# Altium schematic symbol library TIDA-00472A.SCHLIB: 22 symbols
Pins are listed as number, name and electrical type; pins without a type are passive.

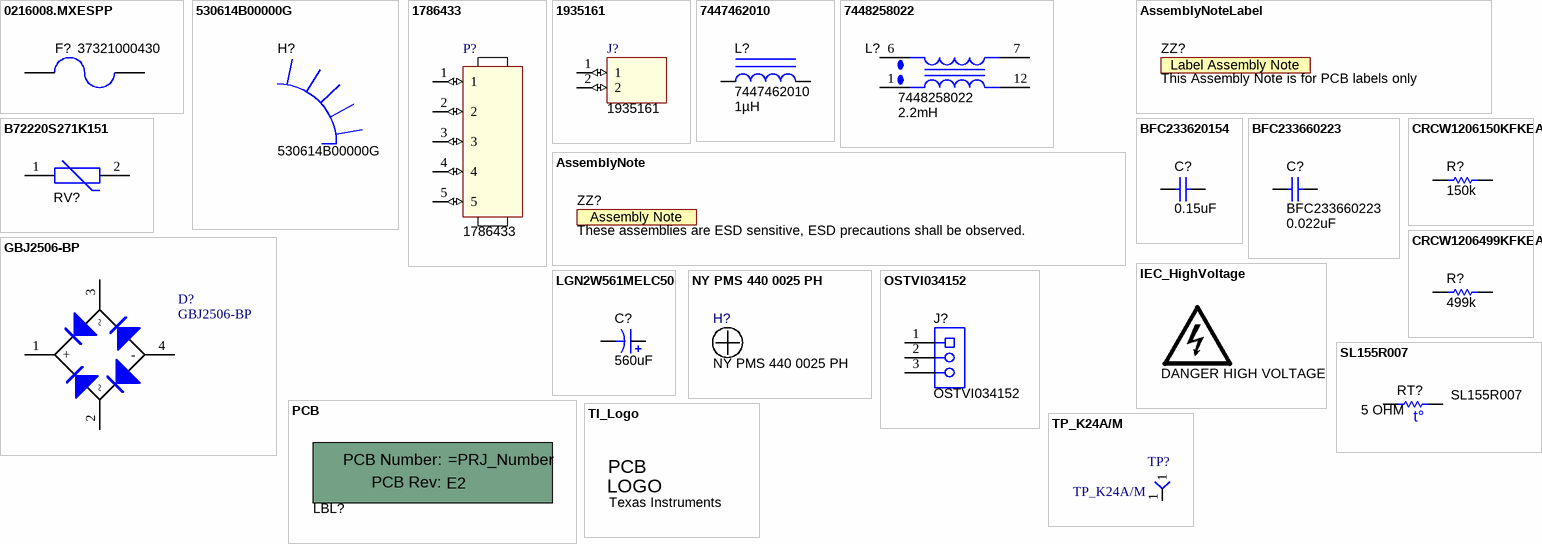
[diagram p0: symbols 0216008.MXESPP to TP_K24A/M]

## 0216008.MXESPP
designator F?, comment 37321000430
LITTELFUSE_373, TH-2P; Manufacturer: Littelfuse Inc; CompType: Fuse; U/M: EA; OpeningTime_200%_max: 30; VDC_V: 250; Irating_A: 8; Rtyp_Ohm: 0.0123; Soldering_Wave_MaxTemp_C: 260; Soldering_Wave_MaxTime_s: 5
footprint FUSE_37321000430 (LITTELFUSE_373, TH-2P)
pins: 1, 2

## 530614B00000G
designator H?
Heat Sink, TO-220, TH; Manufacturer: Aavid; SymbolCreator: a0412235
footprint Aavid_530614B00000G (Aavid)

## 1786433
designator P?
TERM BLOCK HDR 5POS R/A 5.08MM; Manufacturer: PHOENIX CONTACT; SymbolCreator: x0199378; CompType: Terminal Block
footprint PHOENIX_1786433 (TERM BLOCK, HDR, 5POS, R/A 5.08MM)
pins: 1 (io), 2 (io), 3 (io), 4 (io), 5 (io)

## 1935161
designator J?
TERM BLOCK PCB, 2POS, 5.0MM, TH; Manufacturer: PHOENIX CONTACT; SymbolCreator: x0199378; CompType: Terminal Block
footprint Phoenix_1935161 (TERM BLOCK PCB, 2POS, 5.0MM, TH)
pins: 1 (io), 2 (io)

## 7447462010
designator L?  ValueDisplayed: 1µH
Inductor, Unshielded Drum Core, Ferrite, 1uH, 8A, 0.006 ohm, TH; Manufacturer: Wurth Elektronik eiSos; Ind_H: 1.0E-6; Imax_A: 8; Irms: 8.5A @ 40C rise; Isat: 8A @ 10% inductance drop; DCR_ohm: 0.006; U/M: EA
signal-integrity model Inductor
simulation model Inductor
footprint IND_WE-TI_XS
pins: 1, 2

## 7448258022
designator L?  value 2.2mH
FILTER, WE-CMB COMMON MODE POWER LINE CHOKE, 2.2mH, 8A, VERTICAL; Manufacturer: Wurth Elektronics; SymbolCreator: x0199378
footprint WURTH_7448258022 (CHOKE TOROID, 2.2MH, 8A, VERTICAL)
pins: 1, 6, 7, 12 2

## AssemblyNote
designator ZZ?, comment These assemblies are ESD sensitive, ESD precautions shall be observed.  (no BOM)
SymbolCreator: codlsc; CompType: AssemblyNote
footprint AssemblyNote

## AssemblyNoteLabel
designator ZZ?, comment This Assembly Note is for PCB labels only  (no BOM)
SymbolCreator: a0412235
footprint AssemblyNoteLabel

## B72220S271K151
designator RV?  (value not drawn)
VARISTOR, 387V, 8KA, DISC 20MM; Manufacturer: EPCOS Inc; SymbolCreator: x0199378
footprint VAR_B72220S0271K151 (VARISTOR, 275V, 8KA, DISC 20MM)
pins: 1, 2

## BFC233620154
designator C?  value 0.15uF  (hidden comment: BFC233620154)
CAP, FILM, 0.15uF, 310V, 20%, RADIAL-2P; Manufacturer: VISHYA; CompType: Film Capacitor; SymbolCreator: x0199378
footprint B32922_12mm (Epcos film capacitors, 15mm spacing)
pins: 1, 2

## BFC233660223
designator C?  value 0.022uF
CAP, FILM, 0.022uF, 300V, 20%, RADIAL-2P; Manufacturer: VISHYA; CompType: Film Capacitor; SymbolCreator: x0199378
footprint B81123_1800x900x1750 (CAPACITOR, FILM, 4700PF, RADIAL, EPCOS)
pins: 1, 2

## CRCW1206150KFKEA
designator R?  value 150k  (hidden comment: CRCW1206150KFKEA)
RES, 150k ohm, 1%, 0.25W, 1206; Manufacturer: Vishay-Dale; CompType: Resistor; Res_ohm: 150000; Tolerance_%: 1; Power_W: 0.25; VDC_V: 200; TempCo: 100 ppm/C; EIA_Code: E96; U/M: EA
signal-integrity model Resistor
simulation model Resistor
footprint 1206 (1206 from SM-752 data)
footprint 1206M
footprint 1206L
pins: 1, 2

## CRCW1206499KFKEA
designator R?  value 499k  (hidden comment: CRCW1206499KFKEA)
RES, 499k ohm, 1%, 0.25W, 1206; Manufacturer: Vishay-Dale; CompType: Resistor; Res_ohm: 499000; Tolerance_%: 1; Power_W: 0.25; VDC_V: 200; TempCo: 100 ppm/C; EIA_Code: E96; U/M: EA
signal-integrity model Resistor
simulation model Resistor
footprint 1206
footprint 1206M
footprint 1206L
pins: 1, 2

## GBJ2506-BP
designator D?
BRIDGE RECTIFIER, GPP, 25A, 600V, GBJ; Manufacturer: MICRO COMMERCIAL COMPONENTS; SymbolCreator: x0199378
footprint MCC_GBJ2506 (Bridge Rectifier, 4pin , TH)
pins: 1 +, 2 ~, 3 ~, 4 -

## IEC_HighVoltage
designator LOGO?, comment DANGER HIGH VOLTAGE  (no BOM)
IEC 61010-1 High Voltage Warning; SymbolCreator: a0412235
footprint IEC_HighVoltage_Large
footprint IEC_HighVoltage_Medium
footprint IEC_HighVoltage_Small

## LGN2W561MELC50
designator C?  value 560uF  (hidden comment: LGN2W561MELC50)
CAP, ALUMINUM, 560 uF, 450V, 20%, TH; Manufacturer: NICHICON; CompType: Aluminum Capacitor; SymbolCreator: x0199378
footprint CAPPRD1000W150D3500H5000 (Panasonic)
pins: 1 +, 2 -

## NY PMS 440 0025 PH
designator H?
Machine Screw, Round, #4-40 x 1/4, Nylon, Philips panhead; Manufacturer: B&F Fastener Supply; CompType: Hardware; SymbolCreator: codlsc; U/M: EA
footprint NY PMS 440 0025 PH
footprint NY PMS 440 0025 PH_3Donly

## OSTVI034152
designator J?
TERMINAL BLOCK 7.50MM 3POS PCB, TH; Manufacturer: On-Shore Technology; SymbolCreator: x0199378
footprint ONSHORE_OSTVI034152 (TERMINAL BLOCK, 7.5MM PITCH,THRU-3PINS)
pins: 1, 2, 3

## PCB
designator LBL?, comment Printed Circuit Board  (value not drawn)  (mechanical)
Manufacturer: Any; SymbolCreator: a0412235; CompType: PCB
footprint Label_650x200 (Thermal Transfer Label)
1 alternate drawing of the same symbol

## SL155R007
designator RT?  value 5 OHM
CURRENT LIMITER INRUSH 5 OHM 7A; Manufacturer: AMETHERM; CompType: ThermistorNTC; SymbolCreator: x0199378
footprint THERM_B57364S0 (CURRENT LIMITER INRUSH, 2 PIN, TH, EPCOS)
pins: 1, 2

## TI_Logo
designator Logo?, comment Texas Instruments  (no BOM)
Texas Instrument Corporate Signature; SymbolCreator: codlsc
footprint TI_Stacked_SolderMask_Medium
footprint TI_Stacked_Overlay_Small
footprint TI_Stacked_Overlay_Medium
footprint TI_Stacked_Overlay_Small
footprint TI_Horizontal_SolderMask_Medium
footprint TI_Horizontal_SolderMask_Small
footprint TI_Horizontal_Overlay_Medium
footprint TI_Horizontal_Overlay_Small
footprint TI_Symbol_SolderMask_Small
footprint TI_Symbol_Overlay_Medium
footprint TI_Symbol_Overlay_Small
footprint TI_Symbol_SolderMask_Medium

## TP_K24A/M
designator TP?
Pin, Thru Hole, Tin Plate, for 0.062 PCB's; Manufacturer: Vector; PartNumber: K24A/M; area: 0.001 inch; Value: K24A/M
footprint HOLE-70X43
pins: 1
